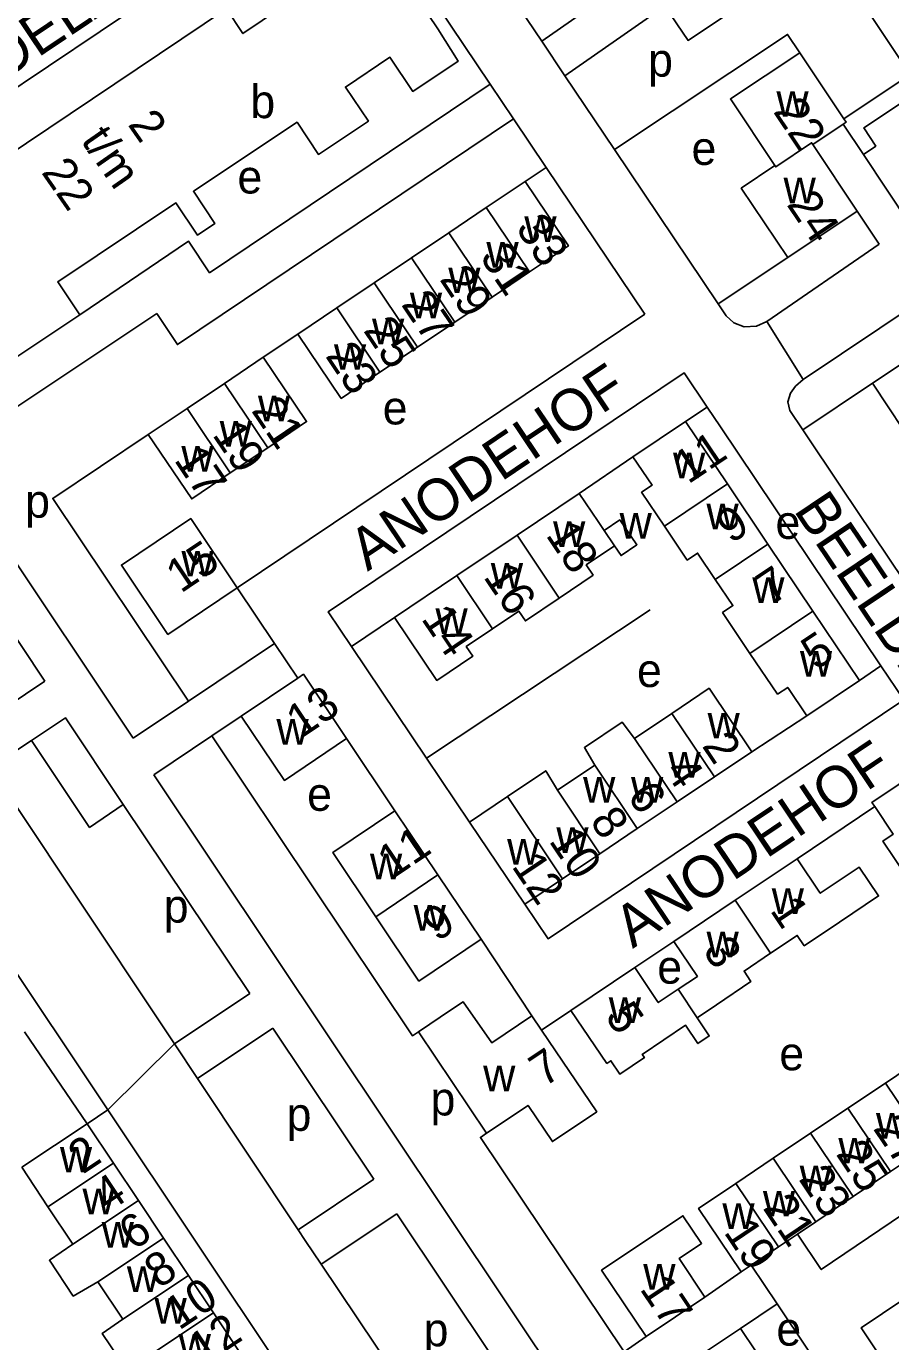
# Model space of a CAD drawing. Extents: x 158356 to 159894, y 383831 to 385260.
# Drawn here: x 158874.6 to 158978.3, y 384426.6 to 384584.4 of the extents above; entities that cross this region are included whole.
import ezdxf

# ---------------------------------------------------------------- set-up
doc = ezdxf.new("R2010")
doc.units = 0
for name, color, linetype in [('BLT_Basislijn', 7, 'Continuous'), ('BLT_Bebouwing', 7, 'Continuous'), ('BLT_Centroide', 7, 'Continuous'), ('BLT_Huisnummer', 7, 'Continuous'), ('BLT_Huisnummer_ tussenligend', 7, 'Continuous'), ('BLT_Huisnummer_reeks', 7, 'Continuous'), ('BLT_Onderverdeling_panden', 7, 'Continuous'), ('BLT_Straatnaam', 7, 'Continuous'), ('BLT_Vlakafsluiter', 7, 'Continuous')]:
    doc.layers.add(name, color=color, linetype=linetype)

msp = doc.modelspace()

# ---------------------------------------------------------------- linework, layer by layer
at = {"layer": 'BLT_Basislijn'}
for p, q in [((158847.11, 384559.33), (158912.8, 384603.45)), ((158936.45, 384582.58), (158931.67, 384589.7)), ((158976.16, 384585.28), (158980.66, 384578.56)), ((158939.24, 384578.42), (158936.45, 384582.58)), ((158945.18, 384569.59), (158939.24, 384578.42)), ((158980.66, 384578.56), (158972.71, 384573.25)), ((158933.08, 384573.25), (158930.29, 384577.4)), ((158936.99, 384567.43), (158933.08, 384573.25)), ((158975.04, 384568.98), (158972.61, 384572.6)), ((158957.63, 384551.05), (158945.18, 384569.59)), ((158934.46, 384565.73), (158936.99, 384567.43)), ((158965.97, 384556.64), (158957.63, 384551.05)), ((158958.58, 384549.63), (158957.63, 384551.05)), ((158890.27, 384549.89), (158864.76, 384532.9)), ((158899.93, 384516.99), (158948.81, 384549.83)), ((158903.05, 384544.65), (158907.21, 384547.44)), ((158976.13, 384541.53), (158967.78, 384535.94)), ((158953.71, 384536.95), (158956.3, 384538.68)), ((158956.3, 384538.68), (158957.89, 384536.32)), ((158967.78, 384535.94), (158966.22, 384538.25)), ((158972.46, 384528.97), (158967.78, 384535.94)), ((158864.76, 384532.9), (158887.45, 384498.95)), ((158940.96, 384528.33), (158947.4, 384532.71)), ((158860.6, 384530.13), (158876.86, 384505.79)), ((158899.93, 384516.99), (158904.41, 384510.32)), ((158922.65, 384496.56), (158949.45, 384514.37)), ((158904.41, 384510.32), (158894.08, 384503.4)), ((158904.41, 384510.32), (158907.19, 384506.18)), ((158913.64, 384509.98), (158922.65, 384496.56)), ((158974.57, 384505.9), (158977.15, 384507.64)), ((158894.08, 384503.4), (158887.45, 384498.95)), ((158900.39, 384501.61), (158896.86, 384499.24)), ((158961.66, 384497.34), (158968.26, 384501.66)), ((158875.24, 384498.7), (158870.32, 384495.41)), ((158896.86, 384499.24), (158889.9, 384494.57)), ((158913.05, 384498.91), (158918.85, 384490.25)), ((158922.65, 384496.56), (158927.79, 384488.9)), ((158901.42, 384468.33), (158886.26, 384491.02)), ((158967.09, 384484.51), (158976.4, 384490.76)), ((158884.41, 384454.37), (158867.61, 384479.52)), ((158929.2, 384474.85), (158935.28, 384465.64)), ((158947.62, 384471.44), (158952.31, 384474.59)), ((158901.42, 384468.33), (158892.38, 384462.29)), ((158904.2, 384464.17), (158895.15, 384458.13)), ((158881.92, 384452.7), (158874.42, 384463.73)), ((158881.92, 384452.7), (158884.41, 384454.37)), ((158959.61, 384341.76), (158884.41, 384454.37)), ((158916.3, 384446.06), (158907.23, 384440)), ((158919.08, 384441.9), (158910.01, 384435.85)), ((158964.71, 384431.12), (158961.59, 384435.75)), ((158960.38, 384434.94), (158956.03, 384431.92)), ((158960.3, 384428.16), (158964.71, 384431.12)), ((158968.44, 384425.56), (158964.71, 384431.12)), ((158948.98, 384427.18), (158946.34, 384425.35))]:
    msp.add_line(p, q, dxfattribs=at)
for points in [[(158936.45, 384582.58), (158952.55, 384593.8), (158955.38, 384589.59), (158973.61, 384601.84), (158975.82, 384598.55), (158988.93, 384607.24)], [(158930.29, 384577.4), (158912.8, 384603.45)], [(158939.24, 384578.42), (158951.24, 384586.79), (158954.02, 384582.66), (158970.5, 384593.72), (158976.16, 384585.28)], [(158967.43, 384581.18), (158965.96, 384583.38), (158945.18, 384569.59)], [(158930.29, 384577.4), (158896.61, 384554.79), (158894.07, 384558.59), (158881.04, 384549.75)], [(158933.08, 384573.25), (158892.75, 384546.18), (158890.27, 384549.89)], [(158948.81, 384549.83), (158936.99, 384567.43)], [(158974.29, 384562.18), (158976.95, 384558.21)], [(158976.95, 384558.21), (158963.45, 384548.93)], [(158984.44, 384547.08), (158981.6, 384551.22), (158967.84, 384542)], [(158963.45, 384548.93), (158962.23, 384548.39), (158960.75, 384548.3), (158959.5, 384548.8), (158958.58, 384549.63)], [(158956.3, 384538.68), (158953.53, 384542.8), (158910.85, 384514.13), (158913.64, 384509.98)], [(158967.84, 384542), (158966.91, 384541.2), (158966.31, 384540.36), (158966, 384539.3), (158966.22, 384538.25)], [(158894.08, 384503.4), (158877.8, 384527.72), (158889.25, 384535.39)], [(158977.15, 384507.64), (158957.89, 384536.32)], [(158991.19, 384501.08), (158972.46, 384528.97)], [(158918.79, 384513.45), (158913.64, 384509.98)], [(158934.42, 384479.05), (158937.22, 384474.91), (158979.89, 384503.56), (158977.15, 384507.64)], [(158876.86, 384505.79), (158867.54, 384499.56)], [(158886.26, 384491.02), (158879.31, 384501.42), (158875.24, 384498.7)], [(158886.26, 384491.02), (158882.21, 384488.25), (158875.24, 384498.7)], [(158921.68, 384463.75), (158920.95, 384463.26), (158896.86, 384499.24)], [(158870.32, 384495.41), (158879.55, 384481.56), (158892.38, 384462.29)], [(158939.31, 384420.63), (158889.9, 384494.57)], [(159009.45, 384467.91), (159012.23, 384463.79), (158970, 384435.22), (158967.14, 384439.48)], [(158936.44, 384463.93), (158939.94, 384466.28)], [(158916.3, 384446.06), (158904.2, 384464.17)], [(158892.38, 384462.29), (158895.15, 384458.13)], [(158895.15, 384458.13), (158907.23, 384440)], [(158946.34, 384425.35), (158929.11, 384451.08), (158929.85, 384451.58)], [(158936.45, 384415.89), (158919.08, 384441.9)], [(158907.23, 384440), (158908.09, 384438.71), (158910.01, 384435.85)], [(158910.01, 384435.85), (158927.42, 384409.86)]]:
    msp.add_lwpolyline(points, dxfattribs=at)
at = {"layer": 'BLT_Bebouwing'}
for p, q in [((158929.81, 384562.61), (158925.32, 384559.6)), ((158925.32, 384559.6), (158920.84, 384556.59)), ((158920.84, 384556.59), (158916.35, 384553.58)), ((158930.5, 384551.88), (158934.99, 384554.89)), ((158916.35, 384553.58), (158911.87, 384550.57)), ((158926.02, 384548.87), (158930.5, 384551.88)), ((158868.26, 384541.24), (158881.04, 384549.75)), ((158921.54, 384545.86), (158926.02, 384548.87)), ((158917.05, 384542.85), (158921.54, 384545.86)), ((158898.39, 384541.52), (158893.91, 384538.51)), ((158953.71, 384536.95), (158947.4, 384532.71)), ((158899.09, 384530.79), (158903.58, 384533.8)), ((158963.58, 384522.25), (158958.73, 384529.47)), ((158940.96, 384528.33), (158933.49, 384523.31)), ((158933.49, 384523.31), (158926.27, 384518.46)), ((158968.99, 384514.2), (158963.58, 384522.25)), ((158926.27, 384518.46), (158918.79, 384513.45)), ((158968.26, 384501.66), (158974.57, 384505.9)), ((158952.06, 384501.94), (158947.58, 384498.93)), ((158957.17, 384494.33), (158961.66, 384497.34)), ((158942.81, 384495.73), (158938.33, 384492.72)), ((158952.69, 384491.32), (158957.17, 384494.33)), ((158947.92, 384488.12), (158952.69, 384491.32)), ((158924.01, 384482.57), (158918.85, 384490.25)), ((158927.79, 384488.9), (158934.42, 384479.05)), ((158943.44, 384485.11), (158947.92, 384488.12)), ((158938.96, 384482.1), (158943.44, 384485.11)), ((158967.09, 384484.51), (158959.66, 384479.52)), ((158929.2, 384474.85), (158924.01, 384482.57)), ((158959.66, 384479.52), (158952.31, 384474.59)), ((158947.62, 384471.44), (158939.94, 384466.28)), ((158936.44, 384463.93), (158935.28, 384465.64)), ((158982.17, 384460.62), (158977.68, 384457.6)), ((158977.68, 384457.6), (158973.2, 384454.59)), ((158973.2, 384454.59), (158968.72, 384451.58)), ((158874.09, 384447.51), (158881.92, 384452.7)), ((158881.92, 384452.7), (158885.08, 384447.97)), ((158968.72, 384451.58), (158964.24, 384448.57)), ((158978.31, 384446.98), (158982.8, 384449.99)), ((158964.24, 384448.57), (158959.75, 384445.56)), ((158877.21, 384442.73), (158874.09, 384447.51)), ((158885.08, 384447.97), (158888.07, 384443.49)), ((158973.83, 384443.97), (158978.31, 384446.98)), ((158891.07, 384439), (158888.07, 384443.49)), ((158969.35, 384440.96), (158973.83, 384443.97)), ((158880.2, 384438.25), (158877.21, 384442.73)), ((158967.14, 384439.48), (158969.35, 384440.96)), ((158891.07, 384439), (158894.07, 384434.5)), ((158964.87, 384437.95), (158967.14, 384439.48)), ((158961.59, 384435.75), (158964.87, 384437.95)), ((158897.06, 384430.02), (158894.07, 384434.5)), ((158886.2, 384429.26), (158883.2, 384433.76)), ((158897.06, 384430.02), (158900.06, 384425.52))]:
    msp.add_line(p, q, dxfattribs=at)
for points in [[(158924, 384584.05), (158916.97, 384594.54), (158900.6, 384583.49), (158898.63, 384586.44), (158858.52, 384559.55), (158857.84, 384560.12), (158856.96, 384560.46), (158856.07, 384560.27), (158855.35, 384559.78), (158854.9, 384559.06), (158854.76, 384558.22), (158855.09, 384557.32), (158856.24, 384555.55), (158856.8, 384555.44), (158858.09, 384556.3), (158865.69, 384544.88)], [(158881.04, 384549.75), (158878.4, 384553.72), (158892.57, 384563.16), (158895.14, 384559.31), (158897.24, 384560.71), (158894.67, 384564.56), (158907.11, 384572.84), (158909.67, 384568.99), (158915.67, 384572.99), (158912.91, 384577.07), (158918.25, 384580.64), (158920.98, 384576.55), (158926.45, 384580.19), (158924, 384584.05)], [(158967.43, 384581.19), (158959.09, 384575.64), (158964.42, 384567.65)], [(158972.71, 384573.25), (158967.43, 384581.19)], [(158983.36, 384574.53), (158980.84, 384572.84), (158979.38, 384575.03), (158975.08, 384572.16), (158976.53, 384569.98), (158975.04, 384568.98)], [(158972.61, 384572.6), (158972.98, 384572.85), (158972.71, 384573.25)], [(158968.97, 384570.17), (158972.61, 384572.6)], [(158974.29, 384562.18), (158968.97, 384570.17)], [(158975.04, 384568.98), (158980.59, 384560.65)], [(158964.42, 384567.65), (158960.39, 384564.93), (158965.97, 384556.64)], [(158934.46, 384565.73), (158929.81, 384562.61)], [(158934.99, 384554.89), (158939.65, 384558.01), (158934.46, 384565.73)], [(158965.97, 384556.64), (158974.29, 384562.18)], [(158911.87, 384550.57), (158907.21, 384547.44)], [(158907.21, 384547.44), (158912.4, 384539.72), (158917.05, 384542.85)], [(158984.44, 384547.08), (158976.13, 384541.53)], [(158903.05, 384544.65), (158898.39, 384541.52)], [(158903.58, 384533.8), (158908.24, 384536.93), (158903.05, 384544.65)], [(158976.13, 384541.53), (158981.71, 384533.17), (158989.69, 384538.5)], [(158893.91, 384538.51), (158889.25, 384535.39)], [(158958.73, 384529.47), (158953.71, 384536.95)], [(158889.25, 384535.39), (158894.46, 384527.67), (158899.09, 384530.79)], [(158947.4, 384532.71), (158949.69, 384529.3), (158948.44, 384528.47), (158951.18, 384524.4)], [(158943.96, 384523.86), (158943.22, 384524.97), (158940.96, 384528.33)], [(158899.93, 384516.99), (158894.34, 384525.31), (158886.03, 384519.72), (158891.61, 384511.41), (158899.93, 384516.99)], [(158943.96, 384523.86), (158945.82, 384525.15), (158947.88, 384522.17), (158945.98, 384520.86), (158945.2, 384522.02)], [(158951.18, 384524.4), (158953.91, 384520.33), (158955.15, 384521.17), (158957.27, 384518.01)], [(158938.56, 384515.76), (158942.61, 384518.53), (158941.8, 384519.74), (158945.2, 384522.02)], [(158957.27, 384518.01), (158959.39, 384514.86), (158958.15, 384514.02), (158961.43, 384509.13)], [(158930.56, 384512.07), (158933.71, 384514.19), (158933.71, 384514.19), (158934.49, 384513.03), (158938.56, 384515.76)], [(158918.79, 384513.45), (158923.87, 384505.89), (158928.19, 384508.79), (158927.4, 384509.95), (158930.56, 384512.07)], [(158974.57, 384505.9), (158968.99, 384514.2)], [(158961.43, 384509.13), (158964.76, 384504.25), (158965.97, 384505.06), (158968.26, 384501.66)], [(158913.05, 384498.91), (158907.86, 384506.63), (158907.19, 384506.18)], [(158907.19, 384506.18), (158900.39, 384501.61)], [(158961.66, 384497.34), (158956.54, 384504.95), (158952.06, 384501.94)], [(158900.39, 384501.61), (158905.58, 384493.89), (158913.05, 384498.91)], [(158947.58, 384498.93), (158946.11, 384500.88), (158941.57, 384497.83), (158942.81, 384495.73)], [(158982.37, 384495.5), (158976.06, 384491.26), (158976.4, 384490.76)], [(158938.33, 384492.72), (158936.93, 384495.06), (158932.33, 384491.96)], [(158932.33, 384491.96), (158927.79, 384488.9)], [(158976.4, 384490.76), (158978.62, 384487.45), (158977.38, 384486.61), (158980.16, 384482.46)], [(158918.85, 384490.25), (158911.38, 384485.23), (158916.54, 384477.55)], [(158963.92, 384473.17), (158967.12, 384475.31), (158967.96, 384474.07), (158972.19, 384476.91), (158976.86, 384480.04), (158974.54, 384483.49), (158969.88, 384480.36), (158967.09, 384484.51)], [(158934.42, 384479.05), (158938.96, 384482.1)], [(158916.54, 384477.55), (158921.72, 384469.83), (158929.2, 384474.85)], [(158952.31, 384474.59), (158955.13, 384470.39), (158952.81, 384468.84)], [(158955.09, 384465.43), (158957.41, 384466.99), (158961.56, 384469.78), (158960.73, 384471.02), (158963.92, 384473.17)], [(158952.81, 384468.84), (158950.44, 384467.25), (158947.62, 384471.44)], [(158935.28, 384465.64), (158930.49, 384462.4), (158927.03, 384467.35), (158925.63, 384466.41), (158921.68, 384463.75)], [(158939.94, 384466.28), (158944.28, 384459.95), (158944.76, 384460.27), (158945.84, 384458.66), (158948.78, 384460.64), (158948.51, 384461.03), (158953.71, 384464.53), (158955.19, 384462.33), (158956.56, 384463.25), (158955.09, 384465.43)], [(158929.85, 384451.58), (158934.82, 384454.91), (158937.73, 384450.58), (158943.06, 384454.16), (158936.44, 384463.93)], [(158921.68, 384463.75), (158929.85, 384451.58)], [(158959.75, 384445.56), (158955.27, 384442.55), (158960.38, 384434.94)], [(158948.98, 384427.18), (158943.64, 384435.13), (158953.4, 384441.67), (158955.63, 384438.35), (158952.93, 384436.54), (158956.03, 384431.92)], [(158880.2, 384438.25), (158877.4, 384436.33), (158880.26, 384432.04), (158883.2, 384433.76)], [(158960.38, 384434.94), (158961.59, 384435.75)], [(158982.44, 384433.38), (158974.76, 384428.22), (158979.03, 384421.87)], [(158956.03, 384431.92), (158948.98, 384427.18)], [(158886.2, 384429.26), (158883.74, 384427.57), (158886.64, 384423.24), (158889.19, 384424.78)], [(158960.3, 384428.16), (158954.91, 384424.54)], [(158968.44, 384425.56), (158964.04, 384422.6), (158962.2, 384425.34), (158960.3, 384428.16)]]:
    msp.add_lwpolyline(points, dxfattribs=at)
at = {"layer": 'BLT_Onderverdeling_panden'}
for p, q in [((158943.96, 384523.86), (158945.2, 384522.02)), ((158938.96, 384482.1), (158932.33, 384491.96)), ((158877.21, 384442.73), (158885.08, 384447.97)), ((158888.07, 384443.49), (158880.2, 384438.25)), ((158883.2, 384433.76), (158891.07, 384439)), ((158894.07, 384434.5), (158886.2, 384429.26)), ((158889.19, 384424.78), (158897.06, 384430.02))]:
    msp.add_line(p, q, dxfattribs=at)
for points in [[(158964.42, 384567.65), (158964.53, 384567.48), (158968.84, 384570.38), (158968.97, 384570.17)], [(158934.99, 384554.89), (158929.81, 384562.61)], [(158930.5, 384551.88), (158925.32, 384559.6)], [(158926.02, 384548.87), (158920.84, 384556.59)], [(158921.54, 384545.86), (158916.35, 384553.58)], [(158917.05, 384542.85), (158911.87, 384550.57)], [(158903.58, 384533.8), (158898.39, 384541.52)], [(158899.09, 384530.79), (158893.91, 384538.51)], [(158958.73, 384529.47), (158951.18, 384524.4)], [(158938.56, 384515.76), (158933.49, 384523.31)], [(158963.58, 384522.25), (158957.27, 384518.01)], [(158930.56, 384512.07), (158926.27, 384518.46)], [(158968.99, 384514.2), (158961.43, 384509.13)], [(158957.17, 384494.33), (158952.06, 384501.94)], [(158952.69, 384491.32), (158947.58, 384498.93)], [(158947.92, 384488.12), (158942.81, 384495.73)], [(158943.44, 384485.11), (158938.33, 384492.72)], [(158924.01, 384482.57), (158916.54, 384477.55)], [(158963.92, 384473.17), (158959.66, 384479.52)], [(158955.09, 384465.43), (158952.81, 384468.84)], [(158982.8, 384449.99), (158977.68, 384457.6)], [(158978.31, 384446.98), (158973.2, 384454.59)], [(158973.83, 384443.97), (158968.72, 384451.58)], [(158969.35, 384440.96), (158964.24, 384448.57)], [(158964.87, 384437.95), (158959.75, 384445.56)]]:
    msp.add_lwpolyline(points, dxfattribs=at)
at = {"layer": 'BLT_Vlakafsluiter'}
for p, q in [((158963.45, 384548.93), (158967.84, 384542)), ((158884.41, 384454.37), (158892.38, 384462.29))]:
    msp.add_line(p, q, dxfattribs=at)

# ---------------------------------------------------------------- texts
at = {"layer": 'BLT_Centroide'}
for s, p in [('p', (158949.22, 384578.32)), ('b', (158901.5, 384573.34)), ('w', (158964.61, 384573.5)), ('e', (158954.43, 384567.73)), ('e', (158899.95, 384564.3)), ('w', (158965.47, 384563.11)), ('w', (158934.37, 384558.48)), ('w', (158929.82, 384555.39)), ('w', (158925.24, 384552.35)), ('w', (158920.64, 384549.32)), ('w', (158916.1, 384546.22)), ('w', (158911.53, 384543.15)), ('w', (158902.41, 384536.98)), ('e', (158917.38, 384536.6)), ('w', (158897.82, 384533.94)), ('w', (158893.23, 384530.92)), ('w', (158952.21, 384530.13)), ('p', (158874.48, 384525.41)), ('w', (158956.22, 384524.01)), ('w', (158945.8, 384522.89)), ('e', (158964.5, 384522.87)), ('w', (158937.82, 384521.9)), ('w', (158893.23, 384518.36)), ('w', (158930.35, 384516.89)), ('w', (158961.72, 384515.19)), ('w', (158923.71, 384511.46)), ('e', (158947.89, 384505.1)), ('w', (158967.43, 384506.36)), ('w', (158956.35, 384498.93)), ('w', (158904.63, 384498.18)), ('w', (158951.65, 384494.23)), ('w', (158941.42, 384491.23)), ('w', (158947.17, 384491.23)), ('e', (158908.31, 384490.25)), ('w', (158938.21, 384485.2)), ('w', (158932.31, 384483.79)), ('w', (158915.85, 384482.04)), ('p', (158891.11, 384476.84)), ('w', (158964.05, 384477.89)), ('w', (158921.09, 384475.87)), ('w', (158956.23, 384472.68)), ('e', (158950.32, 384469.52)), ('w', (158944.5, 384464.8)), ('e', (158964.96, 384459.13)), ('w', (158929.43, 384456.61)), ('p', (158923.12, 384453.71)), ('p', (158905.85, 384451.86)), ('w', (158976.56, 384450.93)), ('w', (158878.65, 384446.87)), ('w', (158972.04, 384447.95)), ('w', (158967.4, 384444.63)), ('w', (158881.36, 384441.86)), ('w', (158962.99, 384441.59)), ('w', (158958.13, 384440.1)), ('w', (158883.66, 384437.85)), ('w', (158886.69, 384432.53)), ('w', (158948.64, 384432.8)), ('w', (158890, 384428.72)), ('p', (158922.29, 384426.02)), ('e', (158964.61, 384426.1)), ('w', (158892.9, 384424.41))]:
    msp.add_text(s, height=4, dxfattribs=at).set_placement(p)
at = {"layer": 'BLT_Huisnummer'}
for s, rotation, p in [('22', 303.8701, (158964.15, 384574.13)), ('24', 303.8701, (158965.77, 384562.99)), ('33', 303.8701, (158933.25, 384560.14)), ('29', 303.8701, (158924.12, 384554.01)), ('25', 303.8701, (158914.98, 384547.88)), ('23', 303.8701, (158910.42, 384544.81)), ('21', 303.8701, (158901.54, 384538.27)), ('11', 33.8701, (158954.03, 384529.37)), ('17', 303.8701, (158892.27, 384532.35)), ('18', 303.8701, (158936.86, 384523.33)), ('15', 33.8701, (158893.15, 384516.28)), ('14', 303.8701, (158921.92, 384513.3)), ('5', 33.8701, (158969.36, 384507.03)), ('13', 33.8701, (158907.57, 384498.87)), ('2', 303.8701, (158955.61, 384498.04)), ('6', 303.8701, (158946.63, 384492.04)), ('11', 33.8701, (158918.52, 384482.02)), ('10', 303.8701, (158937.24, 384486.64)), ('12', 303.8701, (158932.77, 384483.61)), ('1', 303.8701, (158963.77, 384478.31)), ('9', 33.8701, (158923.91, 384474.47)), ('5', 303.8701, (158943.97, 384465.6)), ('7', 33.8701, (158936.73, 384457.03)), ('27', 303.8701, (158976.13, 384452.15)), ('2', 33.6717, (158881.4, 384446.61)), ('23', 303.8701, (158967.2, 384446.08)), ('6', 33.6717, (158887.48, 384437.44)), ('19', 303.8701, (158958.22, 384439.71)), ('10', 33.6717, (158892.95, 384427.87)), ('17', 303.8701, (158948.14, 384432.91))]:
    msp.add_text(s, height=4, rotation=rotation, dxfattribs=at).set_placement(p)
at = {"layer": 'BLT_Huisnummer_ tussenligend'}
for s, rotation, p in [('31', 303.8701, (158928.95, 384556.68)), ('27', 303.8701, (158919.52, 384551)), ('19', 303.8701, (158896.86, 384535.37)), ('9', 33.8701, (158959.17, 384522.21)), ('16', 303.8701, (158929.38, 384518.32)), ('7', 33.8701, (158964.03, 384514.86)), ('4', 303.8701, (158951.11, 384495.04)), ('8', 303.8701, (158942.15, 384489.02)), ('3', 303.8701, (158955.7, 384473.47)), ('25', 303.8701, (158971.67, 384449.09)), ('4', 33.6717, (158884.43, 384442.02)), ('21', 303.8701, (158962.9, 384442.61)), ('8', 33.6717, (158890.54, 384432.87)), ('12', 33.6717, (158895.83, 384423.59))]:
    msp.add_text(s, height=4, rotation=rotation, dxfattribs=at).set_placement(p)
at = {"layer": 'BLT_Huisnummer_reeks'}
for s, p in [('2', (158886.72, 384572.58)), ('t/m', (158881.09, 384570.63)), ('22', (158876.35, 384566.84))]:
    msp.add_text(s, height=4, rotation=304.8063, dxfattribs=at).set_placement(p)
at = {"layer": 'BLT_Straatnaam'}
for s, rotation, p in [('KATHODELAAN', 33.8882, (158852.88, 384565.01)), ('ANODEHOF', 33.8882, (158915.56, 384518.91)), ('BEELDBUISRING', 303.8882, (158966.6, 384526.31)), ('ANODEHOF', 33.8882, (158947.37, 384473.68))]:
    msp.add_text(s, height=5, rotation=rotation, dxfattribs=at).set_placement(p)

doc.saveas('drawing.dxf')
